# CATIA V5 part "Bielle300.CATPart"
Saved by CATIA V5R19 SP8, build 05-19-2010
Part number: Bielle300
Publications: "Demi_longueur_bielle", "Rayon_bielle", "Diam_trou_ext", "Diam_trou_int", "Hauteur_Extremite"
Bounding box of the stored display mesh (mm): x -170 to 170, y -20 to 20, z -10 to 10
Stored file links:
  F:\! CONCEPTION\PROJET\Mécanisme 590\CAO\Bielle300.CATPart
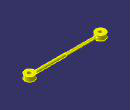
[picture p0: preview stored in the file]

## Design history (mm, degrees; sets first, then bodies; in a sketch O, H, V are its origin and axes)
Parameters
  Demi_longueur_bielle = 150 mm
  Rayon_bielle = 6 mm
  Diam_trou_ext = 40 mm
  Diam_trou_int = 20 mm {= Diam_trou_ext /2}
  Hauteur_Extremite = 10 mm
Body1 (main body)
  Sketch1 on xy-plane, origin (0, 0, 0), H (1, 0, 0), V (0, 1, 0)
    point P1 (-150, 0)
    line L1 (-150, 0) -> (-150, 6)
    line L2 (-150, 6) -> (0, 6)
    line L3 (0, 6) -> (0, 0)
    line L4 (0, 0) -> (-150, 0)
    length L2 = 150 {= Demi_longueur_bielle}
    length L1 = 6 {= Rayon_bielle}
    coincidence: P1 H, L3 V
    vertical: L1 V, L3 V
    horizontal: L2 H, L4 H
  Shaft1: profile Sketch1, axis Sketch1.L4, angle 360
  Sketch2 on xy-plane, origin (0, 0, 0), H (1, 0, 0), V (0, 1, 0)
    circle A1 centre (-150, 0) radius 20
    point P1 (-150, 0)
    reference projected line E1 (-150, 10) -> (-150, -10) from edge [face of Shaft1 from Sketch1.L1 | face of Shaft1 from Sketch1.L2]
    radius A1 = 20 {= Diam_trou_ext /2}
    coincidence: P1 H, P1 E1
  Pad1: profile Sketch2, direction (0, 0, 1), length 10 {= Hauteur_Extremite}, mirrored extent
  Sketch3 on end face of Pad1, origin (0, 0, 10), H (1, 0, 0), V (0, 1, 0)
    circle A1 centre (-150, 0) radius 10
    point P1 (-150, 0)
    reference projected circle E1 centre (-150, 0) radius 20 from edge [face of Pad1 from Sketch2.A1 | end face of Pad1]
    radius A1 = 10 {= Diam_trou_int /2}
    coincidence: P1 H
    concentricity: A1 E1
  Pocket1: profile Sketch3, direction (0, 0, -1), through (limit type 6)
  Mirror1: of Shaft1, Sketch1, Pad1, Sketch2, Pocket1, Sketch3, about yz-plane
